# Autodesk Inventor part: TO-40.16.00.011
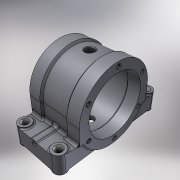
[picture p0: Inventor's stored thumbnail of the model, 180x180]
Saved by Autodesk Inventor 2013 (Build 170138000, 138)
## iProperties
Shininess: 25.0
Length Units: 11269
Angle Units: 11279
Time Units: 11290
Mass Units: 11283
Length Display Precision: 3
Angle Display Precision: 2
Created: 2001-08
Part Number: TO-40.16.00.011
Document SubType Name: Modeling
Designer: SOleg
Density: 1 g/cm^3
Material: Generic
Mass: 2403.54 g
Surface Area: 3195.95 cm^2
Volume: 2403.54 cm^3
Density: 0.0
Volumn: 0.0
Area: 0.0
PropertySet Name: Model Information
Control State: 0
Master: False
Checked Out: True
Checked Out Date: 2008-10-15
Last Check In Date: 2008-10-15
Author: SOleg
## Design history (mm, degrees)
feature "Base1"
thread "Thread1" dims "d0" = 10, "d1" = 0
thread "Thread2" dims "d2" = 10, "d3" = 0
thread "Thread3" dims "d4" = 10, "d5" = 0
thread "Thread4" dims "d6" = 10, "d7" = 0
thread "Thread5" dims "d8" = 10, "d9" = 0
thread "Thread6" dims "d10" = 10, "d11" = 0
thread "Thread7" dims "d12" = 10, "d13" = 0
thread "Thread8" dims "d14" = 10, "d15" = 0
thread "Thread9" dims "d16" = 10, "d17" = 0
thread "Thread10" dims "d18" = 10, "d19" = 0
thread "Thread11" dims "d20" = 10, "d21" = 0
thread "Thread12" dims "d22" = 10, "d23" = 0
body "Solid1"
